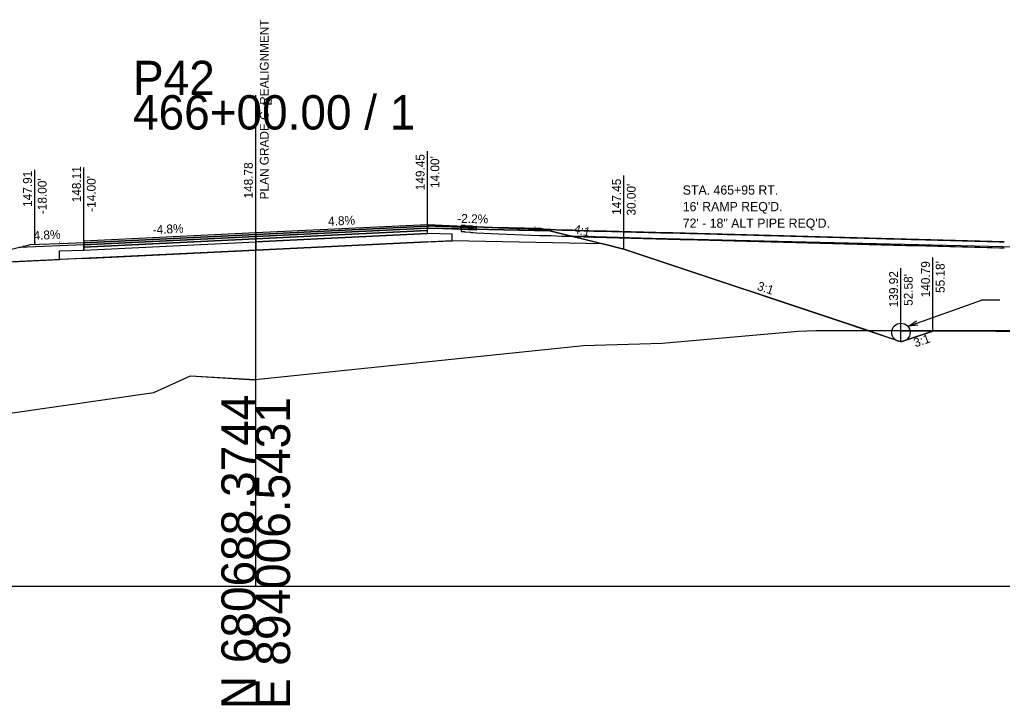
# Model space of a CAD drawing. Extents: x -26 to 4303, y -13 to 10775.
# Drawn here: x 1130.8 to 1210.8, y 4490.3 to 4546.1 of the extents above; entities that cross this region are included whole.
import ezdxf

# ---------------------------------------------------------------- set-up
doc = ezdxf.new("R2010")
doc.units = 0
for name, color, linetype in [('_CIVIL_CONSTRUCTION', 7, 'Continuous'), ('ASHPALT_12_5MM1', 7, 'Continuous'), ('CONST_DCH', 7, 'Continuous'), ('CONST_LV3', 7, 'Continuous'), ('Default', 7, 'Continuous'), ('DTM_CORRIDOR', 7, 'Continuous'), ('DTM_P_FINISHED_GRADE', 7, 'Continuous'), ('DTM_TEMP_DROP', 7, 'Continuous'), ('DTM_X_GROUND', 7, 'Continuous'), ('SLOPE_STAKES_FILL', 7, 'Continuous'), ('X_PROFILES_1', 7, 'Continuous'), ('X_ROW', 7, 'Continuous'), ('XS_CELL', 7, 'Continuous'), ('XS_P_ASPHALT', 7, 'Continuous'), ('XS_P_DR_ASPHALT_B', 7, 'Continuous'), ('XS_P_DR_GRAVEL', 7, 'Continuous'), ('XS_P_DRAINAGE', 7, 'Continuous'), ('XS_P_GROUND', 7, 'Continuous'), ('XS_P_SUBGRADE_GRANULAR', 7, 'Continuous'), ('XS_P_SUBGRADE_LEVELING', 7, 'Continuous'), ('XS_P_SUBGRADE_MILLING', 7, 'Continuous'), ('XS_P_TX_CLEARZONE', 7, 'Continuous'), ('XS_P_TX_FS_BS', 7, 'Continuous'), ('XS_SHEET_EW_TX_AREA', 7, 'Continuous')]:
    doc.layers.add(name, color=color, linetype=linetype)

msp = doc.modelspace()

# ---------------------------------------------------------------- linework, layer by layer
for points in [[(1150, 4528.487), (1136, 4527.814), (1136, 4527.814), (1136, 4527.627), (1150, 4528.299), (1150, 4528.299), (1150, 4528.487), (1150, 4528.487), (1150, 4528.487)], [(1164, 4529.158), (1150, 4528.487), (1150, 4528.487), (1150, 4528.299), (1164, 4528.971), (1164, 4528.971), (1164, 4529.158), (1164, 4529.158), (1164, 4529.158)]]:
    msp.add_lwpolyline(points)
at = {"layer": 'ASHPALT_12_5MM1'}
for p, q in [((1164, 4529.325), (1150, 4528.653)), ((1164, 4529.325), (1164, 4529.155)), ((1164, 4529.325), (1164, 4529.159)), ((1150, 4528.653), (1136, 4527.981)), ((1136, 4527.814), (1136, 4527.981)), ((1136, 4527.815), (1136, 4527.963))]:
    msp.add_line(p, q, dxfattribs=at)
at = {"layer": 'CONST_LV3'}
for points in [[(1164, 4529.45), (1164.311, 4529.444), (1164.516, 4529.439), (1170.77, 4529.16), (1171.278, 4529.149), (1171.786, 4529.138), (1172.646, 4529.093), (1173.11, 4529.083), (1173.575, 4529.072), (1174.039, 4529.062), (1174.943, 4529.018), (1175.374, 4529.009), (1175.804, 4528.999), (1176.765, 4528.958), (1177.178, 4528.949), (1177.558, 4528.934), (1177.969, 4528.925), (1178, 4528.924), (1178.411, 4528.915), (1179, 4528.902), (1179.589, 4528.889), (1180, 4528.88), (1180.002, 4528.88), (1180.004, 4528.88), (1180.591, 4528.864), (1181, 4528.854), (1181.59, 4528.838), (1182, 4528.827), (1182.41, 4528.816), (1183, 4528.8), (1183.59, 4528.785), (1184, 4528.774), (1184.59, 4528.758), (1185, 4528.747), (1185.41, 4528.736), (1186, 4528.721), (1186.591, 4528.705), (1187, 4528.694), (1187.591, 4528.679), (1188, 4528.668), (1188.409, 4528.657), (1189, 4528.641), (1189.591, 4528.625), (1190, 4528.615), (1190.591, 4528.599), (1191, 4528.588), (1191.408, 4528.577), (1192, 4528.561), (1192.592, 4528.546), (1193, 4528.535), (1193.592, 4528.519), (1194, 4528.508), (1194.592, 4528.493), (1195, 4528.482), (1195.593, 4528.466), (1196, 4528.455), (1196.593, 4528.439), (1197, 4528.429), (1197.593, 4528.413), (1198, 4528.402), (1198.407, 4528.391), (1199, 4528.375), (1199.593, 4528.36), (1200, 4528.349), (1200.594, 4528.333), (1201, 4528.322), (1201.406, 4528.311), (1202, 4528.296), (1202.594, 4528.28), (1203, 4528.269), (1203.406, 4528.258), (1204, 4528.243), (1204.594, 4528.227), (1205, 4528.216), (1205.406, 4528.205), (1206, 4528.189), (1206.405, 4528.179), (1207, 4528.163), (1207.595, 4528.147), (1208, 4528.136), (1208.595, 4528.121), (1209, 4528.11), (1209.405, 4528.099), (1210, 4528.083), (1210.596, 4528.067), (1211, 4528.057)], [(1180, 4527.447), (1180, 4527.447), (1178.272, 4527.879)]]:
    msp.add_lwpolyline(points, dxfattribs=at)
at = {"layer": 'Default'}
for points in [[(1164, 4529.325), (1150, 4528.653), (1150, 4528.653), (1150, 4528.487), (1164, 4529.158), (1164, 4529.158), (1164, 4529.325), (1164, 4529.325), (1164, 4529.325)], [(1150, 4528.653), (1136, 4527.981), (1136, 4527.981), (1136, 4527.814), (1150, 4528.487), (1150, 4528.487), (1150, 4528.653), (1150, 4528.653), (1150, 4528.653)]]:
    msp.add_lwpolyline(points, dxfattribs=at)
at = {"layer": 'DTM_P_FINISHED_GRADE'}
for points in [[(1164, 4529.45), (1164.621, 4529.43), (1167.999, 4529.284)], [(1166.731, 4529.391), (1166.755, 4529.389), (1166.932, 4529.386), (1166.963, 4529.384), (1166.979, 4529.383), (1166.983, 4529.383), (1166.995, 4529.383), (1167.004, 4529.382), (1167.054, 4529.379), (1167.067, 4529.379), (1167.105, 4529.37), (1167.504, 4529.331), (1167.533, 4529.329), (1167.541, 4529.328), (1167.542, 4529.328), (1167.568, 4529.325), (1167.576, 4529.324), (1167.609, 4529.321), (1167.643, 4529.318), (1167.653, 4529.317), (1167.669, 4529.315), (1167.686, 4529.314), (1167.696, 4529.313), (1167.728, 4529.31), (1167.999, 4529.284), (1169.785, 4529.202), (1173.112, 4529.083), (1173.575, 4529.072), (1173.576, 4529.072), (1174.039, 4529.062), (1174.943, 4529.018), (1174.944, 4529.018), (1175.374, 4529.009), (1175.375, 4529.009), (1175.804, 4528.999), (1176.765, 4528.958), (1176.766, 4528.958), (1177.178, 4528.949), (1177.179, 4528.949), (1177.56, 4528.934), (1177.969, 4528.925), (1178, 4528.924), (1178.002, 4528.924), (1178.591, 4528.911), (1179, 4528.902), (1179.002, 4528.902), (1179.591, 4528.889), (1180, 4528.88), (1180.002, 4528.88), (1180.004, 4528.88), (1180.591, 4528.864), (1181, 4528.854), (1181.002, 4528.854), (1181.591, 4528.838), (1182, 4528.827), (1182.002, 4528.827), (1182.591, 4528.811), (1183, 4528.8), (1183.002, 4528.8), (1183.592, 4528.785), (1184, 4528.774), (1184.002, 4528.774), (1184.592, 4528.758), (1185, 4528.747), (1185.002, 4528.747), (1185.592, 4528.732), (1186, 4528.721), (1186.002, 4528.721), (1186.592, 4528.705), (1187, 4528.694), (1187.002, 4528.694), (1187.592, 4528.678), (1188, 4528.668), (1188.002, 4528.668), (1188.593, 4528.652), (1189, 4528.641), (1189.002, 4528.641), (1189.593, 4528.625), (1190, 4528.615), (1190.002, 4528.614), (1190.593, 4528.599), (1191, 4528.588), (1191.002, 4528.588), (1191.593, 4528.572), (1192, 4528.561), (1192.002, 4528.561), (1192.593, 4528.546), (1193, 4528.535), (1193.002, 4528.535), (1193.594, 4528.519), (1194, 4528.508), (1194.002, 4528.508), (1194.594, 4528.492), (1195, 4528.482), (1195.002, 4528.482), (1195.594, 4528.466), (1196, 4528.455), (1196.002, 4528.455), (1196.594, 4528.439), (1197, 4528.429), (1197.002, 4528.429), (1197.594, 4528.413), (1198, 4528.402), (1198.002, 4528.402), (1198.595, 4528.386), (1199, 4528.375), (1199.002, 4528.375), (1199.595, 4528.36), (1200, 4528.349), (1200.002, 4528.349), (1200.595, 4528.333), (1201, 4528.322), (1201.002, 4528.322), (1201.595, 4528.306), (1202, 4528.296), (1202.002, 4528.296), (1202.595, 4528.28), (1203, 4528.269), (1203.002, 4528.269), (1203.596, 4528.253), (1204, 4528.243), (1204.002, 4528.243), (1204.596, 4528.227), (1205, 4528.216), (1205.002, 4528.216), (1205.596, 4528.2), (1206, 4528.189), (1206.002, 4528.189), (1206.596, 4528.174), (1207, 4528.163), (1207.002, 4528.163), (1207.596, 4528.147), (1208, 4528.136), (1208.002, 4528.136), (1208.597, 4528.12), (1209, 4528.11), (1209.002, 4528.11), (1209.597, 4528.094), (1210, 4528.083), (1210.002, 4528.083), (1210.597, 4528.067), (1211, 4528.057)]]:
    msp.add_lwpolyline(points, dxfattribs=at)
at = {"layer": 'DTM_X_GROUND'}
msp.add_lwpolyline([(1000, 4527.047), (1012.653, 4521.36), (1015.589, 4520.9), (1030.406, 4519.586), (1040.857, 4518.334), (1059.518, 4517.394), (1100.052, 4515.401), (1117.74, 4513.76), (1122.892, 4513.417), (1126.763, 4513.627), (1141.699, 4515.779), (1144.696, 4517.139), (1149.906, 4516.828), (1149.956, 4516.833), (1176.709, 4519.611), (1183.124, 4519.79), (1194.202, 4520.766), (1195.632, 4520.835), (1210.279, 4520.767), (1231.863, 4520.749), (1269.14, 4520.527), (1289.173, 4520.495), (1300, 4520.407)], dxfattribs=at)
at = {"layer": 'X_ROW'}
for p, q in [((1164, 4529.159), (1164, 4529.325)), ((1173.236, 4529.138), (1164, 4529.325)), ((1164.09, 4529.157), (1164, 4529.159)), ((1173.962, 4528.957), (1164.09, 4529.157)), ((1173.962, 4528.957), (1173.236, 4529.138)), ((1136, 4527.814), (1130.762, 4527.605)), ((1130.762, 4527.605), (1131.557, 4527.803)), ((1134.037, 4527.903), (1131.556, 4527.803)), ((1136, 4527.981), (1134.037, 4527.903)), ((1136, 4527.82), (1136, 4527.981)), ((1136, 4527.815), (1136, 4527.82))]:
    msp.add_line(p, q, dxfattribs=at)
for points in [[(1166, 4528.149), (1166, 4528.149), (1165.995, 4528.678), (1165.995, 4528.678), (1164, 4528.721), (1164, 4528.721), (1164, 4528.721), (1150, 4528.049), (1150, 4528.049), (1150, 4527.383), (1164, 4528.053), (1164, 4528.053), (1166, 4528.149)], [(1136, 4526.709), (1134, 4526.613), (1134.005, 4527.334), (1134.005, 4527.334), (1136, 4527.377), (1136, 4527.377), (1150, 4528.049), (1150, 4528.049), (1150, 4528.049), (1150, 4527.383), (1150, 4527.383), (1136, 4526.709), (1136, 4526.709)]]:
    msp.add_lwpolyline(points, dxfattribs=at)
at = {"layer": 'XS_CELL'}
for p, q in [((1150, 4500), (1150, 4540)), ((1000, 4500), (1150, 4500)), ((1150, 4500), (1300, 4500))]:
    msp.add_line(p, q, dxfattribs=at)
at = {"layer": 'XS_P_ASPHALT'}
msp.add_lwpolyline([(1150, 4528.778), (1136, 4528.106), (1136, 4528.106), (1136, 4527.377), (1150, 4528.049), (1150, 4528.049), (1164, 4528.721), (1164, 4528.721), (1164, 4529.45), (1164, 4529.45), (1164, 4529.45), (1150, 4528.778), (1150, 4528.778)], dxfattribs=at)
at = {"layer": 'XS_P_DR_ASPHALT_B'}
msp.add_lwpolyline([(1164, 4529.325), (1164, 4529.2), (1164.621, 4529.18), (1167.999, 4529.034), (1167.999, 4529.159), (1164.621, 4529.305), (1164, 4529.325)], dxfattribs=at)
at = {"layer": 'XS_P_DR_GRAVEL'}
for points in [[(1166.731, 4529.391), (1166.731, 4528.891), (1166.755, 4528.889), (1166.932, 4528.886), (1166.963, 4528.884), (1166.979, 4528.883), (1166.983, 4528.883), (1166.995, 4528.883), (1167.004, 4528.882), (1167.054, 4528.879), (1167.067, 4528.879), (1167.105, 4528.87), (1167.504, 4528.831), (1167.533, 4528.829), (1167.541, 4528.828), (1167.542, 4528.828), (1167.568, 4528.825), (1167.576, 4528.824), (1167.609, 4528.821), (1167.643, 4528.818), (1167.653, 4528.817), (1167.669, 4528.815), (1167.686, 4528.814), (1167.696, 4528.813), (1167.728, 4528.81), (1167.999, 4528.784), (1169.785, 4528.702), (1173.112, 4528.583), (1173.575, 4528.572), (1173.576, 4528.572), (1174.039, 4528.562), (1174.943, 4528.518), (1174.944, 4528.518), (1175.374, 4528.509), (1175.375, 4528.509), (1175.804, 4528.499), (1176.765, 4528.458), (1176.766, 4528.458), (1177.178, 4528.449), (1177.179, 4528.449), (1177.56, 4528.434), (1177.969, 4528.425), (1178, 4528.424), (1178.002, 4528.424), (1178.591, 4528.411), (1179, 4528.402), (1179.002, 4528.402), (1179.591, 4528.389), (1180, 4528.38), (1180.002, 4528.38), (1180.004, 4528.38), (1180.591, 4528.364), (1181, 4528.354), (1181.002, 4528.354), (1181.591, 4528.338), (1182, 4528.327), (1182.002, 4528.327), (1182.591, 4528.311), (1183, 4528.3), (1183.002, 4528.3), (1183.592, 4528.285), (1184, 4528.274), (1184.002, 4528.274), (1184.592, 4528.258), (1185, 4528.247), (1185.002, 4528.247), (1185.592, 4528.232), (1186, 4528.221), (1186.002, 4528.221), (1186.592, 4528.205), (1187, 4528.194), (1187.002, 4528.194), (1187.592, 4528.178), (1188, 4528.168), (1188.002, 4528.168), (1188.593, 4528.152), (1189, 4528.141), (1189.002, 4528.141), (1189.593, 4528.125), (1190, 4528.115), (1190.002, 4528.114), (1190.593, 4528.099), (1191, 4528.088), (1191.002, 4528.088), (1191.593, 4528.072), (1192, 4528.061), (1192.002, 4528.061), (1192.593, 4528.046), (1193, 4528.035), (1193.002, 4528.035), (1193.594, 4528.019), (1194, 4528.008), (1194.002, 4528.008), (1194.594, 4527.992), (1195, 4527.982), (1195.002, 4527.982), (1195.594, 4527.966), (1196, 4527.955), (1196.002, 4527.955), (1196.594, 4527.939), (1197, 4527.929), (1197.002, 4527.929), (1197.594, 4527.913), (1198, 4527.902), (1198.002, 4527.902), (1198.595, 4527.886), (1199, 4527.875), (1199.002, 4527.875), (1199.595, 4527.86), (1200, 4527.849), (1200.002, 4527.849), (1200.595, 4527.833), (1201, 4527.822), (1201.002, 4527.822), (1201.595, 4527.806), (1202, 4527.796), (1202.002, 4527.796), (1202.595, 4527.78), (1203, 4527.769), (1203.002, 4527.769), (1203.596, 4527.753), (1204, 4527.743), (1204.002, 4527.743), (1204.596, 4527.727), (1205, 4527.716), (1205.002, 4527.716), (1205.596, 4527.7), (1206, 4527.689), (1206.002, 4527.689), (1206.596, 4527.674), (1207, 4527.663), (1207.002, 4527.663), (1207.596, 4527.647), (1208, 4527.636), (1208.002, 4527.636), (1208.597, 4527.62), (1209, 4527.61), (1209.002, 4527.61), (1209.597, 4527.594), (1210, 4527.583), (1210.002, 4527.583), (1210.597, 4527.567), (1211, 4527.557)], [(1211, 4528.057), (1210.597, 4528.067), (1210.002, 4528.083), (1210, 4528.083), (1209.597, 4528.094), (1209.002, 4528.11), (1209, 4528.11), (1208.597, 4528.12), (1208.002, 4528.136), (1208, 4528.136), (1207.596, 4528.147), (1207.002, 4528.163), (1207, 4528.163), (1206.596, 4528.174), (1206.002, 4528.189), (1206, 4528.189), (1205.596, 4528.2), (1205.002, 4528.216), (1205, 4528.216), (1204.596, 4528.227), (1204.002, 4528.243), (1204, 4528.243), (1203.596, 4528.253), (1203.002, 4528.269), (1203, 4528.269), (1202.595, 4528.28), (1202.002, 4528.296), (1202, 4528.296), (1201.595, 4528.306), (1201.002, 4528.322), (1201, 4528.322), (1200.595, 4528.333), (1200.002, 4528.349), (1200, 4528.349), (1199.595, 4528.36), (1199.002, 4528.375), (1199, 4528.375), (1198.595, 4528.386), (1198.002, 4528.402), (1198, 4528.402), (1197.594, 4528.413), (1197.002, 4528.429), (1197, 4528.429), (1196.594, 4528.439), (1196.002, 4528.455), (1196, 4528.455), (1195.594, 4528.466), (1195.002, 4528.482), (1195, 4528.482), (1194.594, 4528.492), (1194.002, 4528.508), (1194, 4528.508), (1193.594, 4528.519), (1193.002, 4528.535), (1193, 4528.535), (1192.593, 4528.546), (1192.002, 4528.561), (1192, 4528.561), (1191.593, 4528.572), (1191.002, 4528.588), (1191, 4528.588), (1190.593, 4528.599), (1190.002, 4528.614), (1190, 4528.615), (1189.593, 4528.625), (1189.002, 4528.641), (1189, 4528.641), (1188.593, 4528.652), (1188.002, 4528.668), (1188, 4528.668), (1187.592, 4528.678), (1187.002, 4528.694), (1187, 4528.694), (1186.592, 4528.705), (1186.002, 4528.721), (1186, 4528.721), (1185.592, 4528.732), (1185.002, 4528.747), (1185, 4528.747), (1184.592, 4528.758), (1184.002, 4528.774), (1184, 4528.774), (1183.592, 4528.785), (1183.002, 4528.8), (1183, 4528.8), (1182.591, 4528.811), (1182.002, 4528.827), (1182, 4528.827), (1181.591, 4528.838), (1181.002, 4528.854), (1181, 4528.854), (1180.591, 4528.864), (1180.004, 4528.88), (1180.002, 4528.88), (1180, 4528.88), (1179.591, 4528.889), (1179.002, 4528.902), (1179, 4528.902), (1178.591, 4528.911), (1178.002, 4528.924), (1178, 4528.924), (1177.969, 4528.925), (1177.56, 4528.934), (1177.179, 4528.949), (1177.178, 4528.949), (1176.766, 4528.958), (1176.765, 4528.958), (1175.804, 4528.999), (1175.375, 4529.009), (1175.374, 4529.009), (1174.944, 4529.018), (1174.943, 4529.018), (1174.039, 4529.062), (1173.576, 4529.072), (1173.575, 4529.072), (1173.112, 4529.083), (1169.785, 4529.202), (1167.999, 4529.284), (1167.728, 4529.31), (1167.696, 4529.313), (1167.686, 4529.314), (1167.669, 4529.315), (1167.653, 4529.317), (1167.643, 4529.318), (1167.609, 4529.321), (1167.576, 4529.324), (1167.568, 4529.325), (1167.542, 4529.328), (1167.541, 4529.328), (1167.533, 4529.329), (1167.504, 4529.331), (1167.105, 4529.37), (1167.067, 4529.379), (1167.054, 4529.379), (1167.004, 4529.382), (1166.995, 4529.383), (1166.983, 4529.383), (1166.979, 4529.383), (1166.963, 4529.384), (1166.932, 4529.386), (1166.755, 4529.389), (1166.731, 4529.391)]]:
    msp.add_lwpolyline(points, dxfattribs=at)
at = {"layer": 'XS_P_DRAINAGE'}
for p in [(1203.194, 4521.199), (1210.631, 4523.301)]:
    msp.add_line(p, (1209.131, 4523.301), dxfattribs=at)
msp.add_lwpolyline([(1203.964, 4521.273), (1203.194, 4521.199), (1203.838, 4521.627)], dxfattribs=at)
msp.add_circle((1202.576, 4520.673), 0.75, dxfattribs=at)
at = {"layer": 'XS_P_GROUND'}
for points in [[(1202.576, 4519.923), (1202.576, 4519.923), (1180, 4527.447), (1180, 4527.447), (1173.962, 4528.957)], [(1202.576, 4519.923), (1205.181, 4520.791)]]:
    msp.add_lwpolyline(points, dxfattribs=at)
at = {"layer": 'XS_P_SUBGRADE_GRANULAR'}
for points in [[(1164, 4528.053), (1164, 4528.053), (1150, 4527.383)], [(1136, 4526.709), (1150, 4527.383), (1150, 4527.383)]]:
    msp.add_lwpolyline(points, dxfattribs=at)
at = {"layer": 'XS_P_SUBGRADE_LEVELING'}
for points in [[(1164, 4529.45), (1150, 4528.778), (1150, 4528.778), (1150, 4528.653), (1164, 4529.325), (1164, 4529.325), (1164, 4529.45), (1164, 4529.45), (1164, 4529.45)], [(1150, 4528.778), (1136, 4528.106), (1136, 4528.106), (1136, 4527.981), (1150, 4528.653), (1150, 4528.653), (1150, 4528.778), (1150, 4528.778), (1150, 4528.778)]]:
    msp.add_lwpolyline(points, dxfattribs=at)
at = {"layer": 'XS_P_SUBGRADE_MILLING'}
for points in [[(1164, 4528.971), (1150, 4528.299), (1150, 4528.299), (1150, 4528.049), (1164, 4528.721), (1164, 4528.721), (1164, 4528.971), (1164, 4528.971), (1164, 4528.971)], [(1150, 4528.299), (1136, 4527.627), (1136, 4527.627), (1136, 4527.377), (1150, 4528.049), (1150, 4528.049), (1150, 4528.299), (1150, 4528.299), (1150, 4528.299)]]:
    msp.add_lwpolyline(points, dxfattribs=at)
at = {"layer": 'XS_P_TX_CLEARZONE'}
for p, q in [((1164, 4529.45), (1164, 4535.45)), ((1164, 4529.45), (1164, 4535.45)), ((1164, 4529.45), (1164, 4535.45)), ((1136, 4528.106), (1136, 4534.106)), ((1136, 4528.106), (1136, 4534.106)), ((1136, 4528.106), (1136, 4534.106)), ((1150, 4528.778), (1150, 4534.778)), ((1150, 4528.778), (1150, 4534.778)), ((1150, 4528.778), (1150, 4534.778)), ((1132, 4527.914), (1132, 4533.914)), ((1132, 4527.914), (1132, 4533.914)), ((1180, 4527.447), (1180, 4533.447)), ((1180, 4527.447), (1180, 4533.447)), ((1180, 4527.447), (1180, 4533.447)), ((1205.181, 4520.791), (1205.181, 4526.791)), ((1205.181, 4520.791), (1205.181, 4526.791)), ((1202.576, 4519.923), (1202.576, 4525.923)), ((1202.576, 4519.923), (1202.576, 4525.923)), ((1202.576, 4519.923), (1202.576, 4525.923))]:
    msp.add_line(p, q, dxfattribs=at)
at = {"layer": 'XS_SHEET_EW_TX_AREA'}
for points in [[(1178.272, 4527.879), (1166, 4528.149), (1165.995, 4528.678), (1164, 4528.721), (1164, 4529.158), (1173.962, 4528.957)], [(1175.807, 4528.507), (1180, 4527.447), (1199.895, 4520.821), (1250.502, 4520.821), (1281.73, 4520.394), (1259.496, 4526.178), (1242.835, 4526.875), (1182.296, 4528.319)], [(1092.563, 4515.77), (1100.052, 4515.401), (1108.896, 4514.581), (1117.74, 4513.76), (1122.892, 4513.417), (1126.763, 4513.627), (1141.699, 4515.779), (1144.696, 4517.139), (1149.956, 4516.833), (1176.709, 4519.611), (1183.124, 4519.79), (1188.663, 4520.278), (1194.202, 4520.766), (1195.632, 4520.835), (1199.895, 4520.821), (1180, 4527.447), (1178.272, 4527.879), (1166, 4528.149), (1150, 4527.383), (1125.084, 4526.185), (1120, 4524.914)], [(1125.084, 4526.185), (1134, 4526.613), (1134.005, 4527.334), (1136, 4527.377), (1136, 4527.814), (1130.762, 4527.605)], [(1205.181, 4520.791), (1202.576, 4519.923), (1199.887, 4520.824)]]:
    msp.add_lwpolyline(points, close=True, dxfattribs=at)

# ---------------------------------------------------------------- texts
at = {"layer": '_CIVIL_CONSTRUCTION'}
for p in [(1163.961, 4529.39), (1149.961, 4528.718), (1165.956, 4528.618), (1168.882, 4529), (1168.882, 4529), (1168.882, 4529), (1168.903, 4528.994), (1168.903, 4528.994), (1168.903, 4528.991), (1131.018, 4527.65), (1131.018, 4527.65), (1131.018, 4527.65), (1131.039, 4527.656), (1131.039, 4527.656), (1131.039, 4527.656), (1133.961, 4527.966), (1133.961, 4527.95), (1133.961, 4527.95), (1133.961, 4527.95), (1133.961, 4527.95), (1133.961, 4527.95), (1133.961, 4527.95), (1135.961, 4528.046), (1135.961, 4528.046), (1135.961, 4528.046), (1135.961, 4528.046), (1135.961, 4528.046), (1135.961, 4528.046), (1135.961, 4528.046), (1133.966, 4527.274), (1133.966, 4527.274)]:
    msp.add_text('X', height=0.12, dxfattribs=at).set_placement(p)
at = {"layer": 'CONST_DCH'}
msp.add_text('X', height=0.12, dxfattribs=at).set_placement((1202.537, 4519.863))
msp.add_text('X', height=0.12, dxfattribs=at).set_placement((1202.537, 4519.863))
at = {"layer": 'DTM_CORRIDOR'}
for p in [(1205.086, 4520.712), (1205.142, 4520.731)]:
    msp.add_text('X', height=0.12, dxfattribs=at).set_placement(p)
at = {"layer": 'DTM_TEMP_DROP'}
for p in [(1167.961, 4529.302), (1167.961, 4529.302), (1167.961, 4529.302), (1167.961, 4529.302), (1167.961, 4529.299), (1172.719, 4529.198), (1131.961, 4527.886), (1131.961, 4527.854), (1131.961, 4527.854), (1131.961, 4527.854), (1131.961, 4527.854), (1131.961, 4527.854)]:
    msp.add_text('X', height=0.12, dxfattribs=at).set_placement(p)
at = {"layer": 'SLOPE_STAKES_FILL'}
msp.add_text('X', height=0.12, dxfattribs=at).set_placement((1179.961, 4527.387))
at = {"layer": 'X_PROFILES_1'}
msp.add_text('X', height=0.12, dxfattribs=at).set_placement((1169.206, 4528.991))
at = {"layer": 'XS_CELL'}
for s, p in [('P42', (1140, 4540)), ('466+00.00 / 1', (1140, 4537.2))]:
    msp.add_text(s, height=2.8, dxfattribs=at).set_placement(p)
for s, p in [('N 680688.3744', (1150, 4490)), ('E 894006.5431', (1152.8, 4490))]:
    msp.add_text(s, height=2.8, rotation=90, dxfattribs=at).set_placement(p)
at = {"layer": 'XS_P_DRAINAGE'}
for s, p in [('STA. 465+95 RT.', (1184.797, 4531.9)), ("16' RAMP REQ'D.", (1184.797, 4530.55)), ('72\' - 18" ALT PIPE REQ\'D.', (1184.797, 4529.2))]:
    msp.add_text(s, height=0.75, dxfattribs=at).set_placement(p)
at = {"layer": 'XS_P_TX_CLEARZONE'}
for s, p in [('PLAN GRADE C  REALIGNMENT', (1151.056, 4531.511)), ('L', (1151.306, 4539.156)), ('149.45', (1163.76, 4532.255)), ('149.45', (1163.76, 4532.255)), ('149.45', (1163.76, 4532.255)), ("14.00'", (1164.96, 4532.436)), ("14.00'", (1164.96, 4532.436)), ("14.00'", (1164.96, 4532.436)), ('148.11', (1135.76, 4531.273)), ('148.11', (1135.76, 4531.273)), ('148.11', (1135.76, 4531.273)), ('148.78', (1149.76, 4531.583)), ('148.78', (1149.76, 4531.583)), ('148.78', (1149.76, 4531.583)), ('147.91', (1131.76, 4530.9)), ('147.91', (1131.76, 4530.9)), ('147.91', (1131.76, 4530.9)), ("-14.00'", (1136.96, 4530.502)), ("-14.00'", (1136.96, 4530.502)), ("-14.00'", (1136.96, 4530.502)), ("-18.00'", (1132.96, 4530.31)), ("-18.00'", (1132.96, 4530.31)), ("-18.00'", (1132.96, 4530.31)), ('147.45', (1179.76, 4530.252)), ('147.45', (1179.76, 4530.252)), ('147.45', (1179.76, 4530.252)), ("30.00'", (1180.96, 4530.195)), ("30.00'", (1180.96, 4530.195)), ("30.00'", (1180.96, 4530.195)), ('140.79', (1204.941, 4523.533)), ('140.79', (1204.941, 4523.533)), ("55.18'", (1206.141, 4523.89)), ("55.18'", (1206.141, 4523.89)), ('139.92', (1202.336, 4522.727)), ('139.92', (1202.336, 4522.727)), ('139.92', (1202.336, 4522.727)), ("52.58'", (1203.536, 4522.84)), ("52.58'", (1203.536, 4522.84)), ("52.58'", (1203.536, 4522.84))]:
    msp.add_text(s, height=0.72, rotation=90, dxfattribs=at).set_placement(p)
at = {"layer": 'XS_P_TX_FS_BS'}
for s, rotation, p in [('4.8%', 2.74809, (1155.913, 4529.363)), ('-2.2%', 358.72094, (1166.419, 4529.607)), ('-4.8%', 2.74809, (1141.619, 4528.676)), ('4:1', 345.96376, (1175.858, 4528.792)), ('4.8%', 2.74809, (1131.913, 4528.211)), ('3:1', 341.56677, (1190.802, 4524.163)), ('3:1', 18.43493, (1203.752, 4519.462))]:
    msp.add_text(s, height=0.72, rotation=rotation, dxfattribs=at).set_placement(p)

doc.saveas('drawing.dxf')
